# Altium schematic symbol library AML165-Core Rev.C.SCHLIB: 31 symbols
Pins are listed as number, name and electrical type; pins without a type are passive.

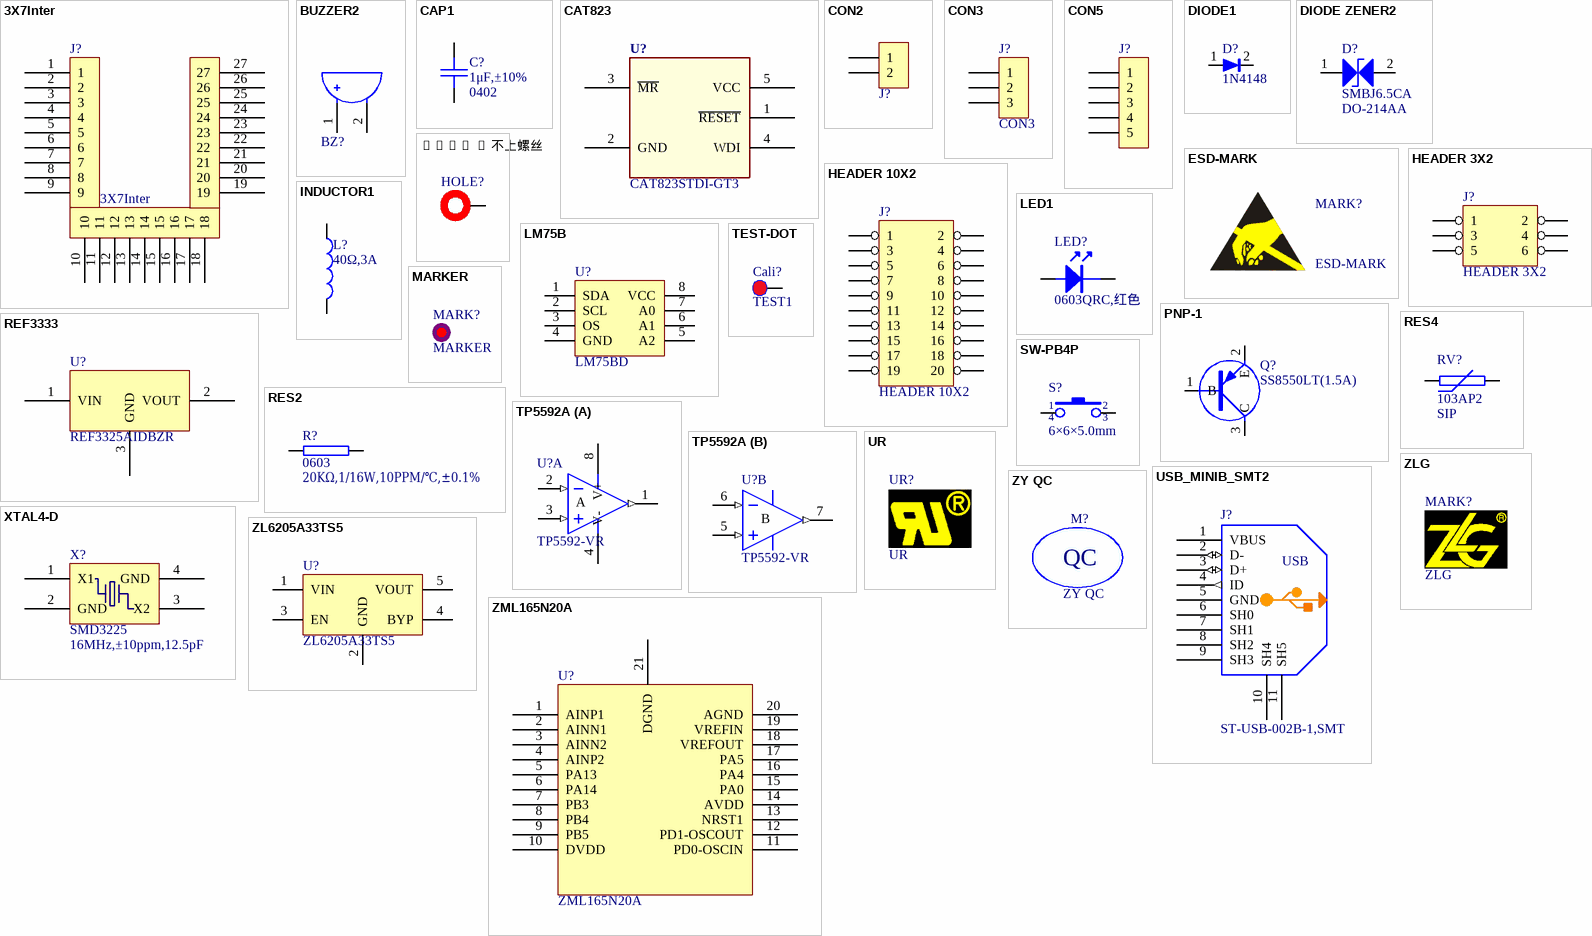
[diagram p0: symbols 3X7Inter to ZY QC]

## 3X7Inter
designator J?
物料代码: 1.10.11.0074
footprint SIP-27 2.54C (Footprint not found)
footprint SIP-27 2.54C
pins: 1, 2, 3, 4, 5, 6, 7, 8, 9, 10, 11, 12, 13, 14, 15, 16, 17, 18, 19, 20, 21, 22, 23, 24, 25, 26, 27

## BUZZER2
designator BZ?  (value not drawn)
Buzzer有极性; 物料代码: 1.06.09.0016; Value: AS-905I-LF,无源; 名称: 讯响器; 厂商: 常州笠翔; 型号: AS-905I-LF,无源,Ф9×4.8mm; 贴片和直插: THT; PCB备注: Flq-Shcj-Twrj-150113; 器件优选方案: 量产物料,优先选用
footprint BUZZ-4/9
pins: 1 A, 2 B
2 alternate drawings of the same symbol

## CAP1
designator C?, comment 封装: 0402  (hidden comment: 1μF,±10%)
GRM155R61C105KA12D,1μF,±10% ,16V,X5R,0402,muRata,RoHS; 物料代码: 1.02.17.0092; 名称: 电容; 贴片和直插: SMT; PCB备注: 无数据手册，依据采购部提供的信息添加的封装。; 器件优选方案: 正常状态，可以选用
footprint 0402CL
footprint 0402C
pins: 1, 2
2 alternate drawings of the same symbol

## CAT823
designator U?, comment CAT823STDI-GT3
1.05.07.0025
footprint SOT-23-5
pins: 1 ~{RESET}, 2 GND, 3 ~{MR}, 4 WDI, 5 VCC

## CON2
designator J?, comment DG127-5.08-02P-14-00AH,180°  (value not drawn)
DG127-5.08-02P-14-00AH,180°,绿色,DEGSON,RoHS; 物料代码: 1.10.06.0070; 名称: 端子; 贴片和直插: THT; PCB备注: xhm-lq-wyy-150126 yyf改名称180925; 器件优选方案: 正常状态，可以选用
footprint CON508P1016L810W110D15S-2DIP
pins: 1, 2
2 alternate drawings of the same symbol

## CON3
designator J?
Connector
footprint SIP-3-2.54
pins: 1, 2, 3
2 alternate drawings of the same symbol

## CON5
designator J?
Connector; 物料代码: 1.10.03.0015
footprint SIP-5-2.54-6.0-R90 (引脚伸出部分为6.0mm)
pins: 1, 2, 3, 4, 5
2 alternate drawings of the same symbol

## DIODE1
designator D?  value 1N4148  (hidden comment: DIODE1)
1N4148,SOD-323,RoHS; 物料代码: 1.04.07.0027; 名称: 二极管; 设备封装名称: SOD-323_1N4148; 贴片和直插: SMT
footprint SOD-323
pins: 1, 2
2 alternate drawings of the same symbol

## DIODE ZENER2
designator D?, comment 封装: DO-214AA  (hidden comment: SMBJ6.5CA)
SMBJ6.5CA,DO-214AA,君耀,RoHS; 物料代码: 1.04.03.0003; 名称: TVS瞬态抑制二极管; 设备封装名称: DO-214AA_SMBJ6.5CA; 贴片和直插: SMT; 器件优选方案: 正常状态，可以选用
footprint SOD-1812
pins: 1 A, 2 K
2 alternate drawings of the same symbol

## ESD-MARK
designator MARK?
footprint ZY_ESD-7
2 alternate drawings of the same symbol

## HEADER 3X2
designator J?
footprint IDC-6-2.54
pins: 1, 2, 3, 4, 5, 6
2 alternate drawings of the same symbol

## HEADER 10X2
designator J?
物料代码: 1.10.03.0016
footprint IDC-20-2.54-R90
pins: 1, 2, 3, 4, 5, 6, 7, 8, 9, 10, 11, 12, 13, 14, 15, 16, 17, 18, 19, 20
2 alternate drawings of the same symbol

## HOLE - 不上螺丝
designator HOLE?  (no BOM)
footprint HOLE-2.2
footprint HOLE-3.2
pins: 1

## INDUCTOR1
designator L?, comment 40Ω,3A
40Ω,3A,DCR35mΩ,BH03Y314S-40R,SMD,0603,丰晶,RoHS; 物料代码: 1.03.03.0011; 名称: 磁珠; 封装: 0603; 贴片和直插: SMT; 器件优选方案: 正常状态，可以选用
footprint 0603L
pins: 1, 2
2 alternate drawings of the same symbol

## LED1
designator LED?, comment 0603QRC,红色
0603QRC,红色,0603,创光,RoHS; 物料代码: 1.04.05.0008; 名称: 发光二极管; 封装: 0603; 设备封装名称: LED0603-RED; 贴片和直插: SMT; 器件优选方案: 正常状态，可以选用
footprint LED-0603
pins: 1, 2
2 alternate drawings of the same symbol

## LM75B
designator U?  value LM75BD  (hidden comment: LM75B)
LM75BD,SO-9,NXP,RoHS; 物料代码: 1.05.10.0602; 名称: IC; 封装: SO-8; 贴片和直插: SMT; 器件优选方案: 样品物料,谨慎选用
footprint SOIC127P600X175-8N
pins: 1 SDA, 2 SCL, 3 OS, 4 GND, 5 A2, 6 A1, 7 A0, 8 VCC
2 alternate drawings of the same symbol

## MARKER
designator MARK?  (no BOM)
footprint MARKER-C-1.0M
footprint MARKER-C-0.8M
pins: 0

## PNP-1
designator Q?  value SS8550LT(1.5A)  (hidden comment: PNP-1)
PNP Transistor; 物料代码: 1.04.09.0002; 名称: 三极管; 封装: SOT-23; 设备封装名称: SOT-23_SS8550LT; 厂商: 江苏长电; 贴片和直插: SMT
footprint SOT-23
pins: 1 B, 2 E, 3 C
2 alternate drawings of the same symbol

## REF3333
designator U?, comment REF3325AIDBZR
REF3325AIDBZR,SOT-23,TI; 物料代码: 1.05.10.0334; 名称: 集成电路; 设备封装名称: SOT-23_REF3325AIDBZR; 贴片和直插: SMT; 器件优选方案: 量产物料,优先选用
footprint SOT-23
pins: 1 VIN, 2 VOUT, 3 GND
2 alternate drawings of the same symbol

## RES2
designator R?, comment 封装: 0603  型号: 20KΩ,1/16W,10PPM/℃,±0.1%  (hidden comment: 20KΩ,1/16W)
20KΩ,1/16W,10PPM/℃,±0.1%,0603,Viking,RoHS; 物料代码: 1.01.01.0207; 名称: 电阻; 贴片和直插: SMT; 器件优选方案: 临时/偏门物料/不主推物料，谨慎选用
footprint 0603R
pins: 1, 2
2 alternate drawings of the same symbol

## RES4
designator RV?, comment 封装: SIP  (hidden comment: 103AP2)
103AP2,SIP,semitec,RoHS; 物料代码: 1.01.14.0020; 名称: 热敏电阻(临时); 贴片和直插: THT; PCB备注: 171205CZY; 器件优选方案: 临时/偏门物料/不主推物料，谨慎选用
footprint RESRR254W35L380T260H850P
pins: 1, 2

## SW-PB4P
designator S?, comment 6×6×5.0mm
TS0641-0501B,6×6×5.0mm,黑色,SMD,卷带装,RoHS; 物料代码: 1.09.01.0003; 名称: 轻触开关; 贴片和直插: SMT; 器件优选方案: 正常状态，可以选用
footprint KEY-6S
pins: 1, 2, 3, 4
2 alternate drawings of the same symbol

## TEST-DOT
designator Cali?, comment TEST1  (no BOM)
footprint PAD-40 (TEST-P)
footprint PAD-50 (TEST-P)
footprint PAD-25/40
footprint PAD-35/50
pins: 1

## TP5592A
designator U?, comment TP5592-VR
TP5592-VR,MSOP-8,3PEAK,RoHS; 物料代码: 1.05.20.0102; 名称: 集成电路(临时); 贴片和直插: SMT; PCB备注: 170810lmd; 器件优选方案: 临时/偏门物料/不主推物料，谨慎选用
footprint SOP65P490X120-8N
part A pins: 1 OUT (out), 2 IN- (in), 3 IN+ (in), 4 V- (power), 8 V+ (power)
part B pins: 5 IN+ (in), 6 IN- (in), 7 OUT (out)

## UR
designator UR?
footprint ZY_UR-3X2
footprint ZY_UR-4X3

## USB_MINIB_SMT2
designator J?, comment ST-USB-002B-1,SMT
ST-USB-002B-1,SMT,SUNGTECH,MicroUSB-A; 物料代码: 20.02.00033; 名称: 连接器; PCB备注: 190710lmd; 器件优选方案: 通用物料
footprint MICROUSB-ST-USB-002B-1
pins: 1 VBUS, 2 D- (io), 3 D+ (io), 4 ID (out), 5 GND (power), 6 SH0, 7 SH1, 8 SH2, 9 SH3, 10 SH4, 11 SH5

## XTAL4-D
designator X?, comment 封装: SMD3225  型号: 16MHz,±10ppm,12.5pF  (hidden comment: JYD3A1C7G5-12.5-16.000,16.0000MHz)
JYD3A1C7G5-12.5-16.000,16.0000MHz,±10ppm,12.5pF,-40~85℃,SMD3225,JYEG,RoHS; 物料代码: 1.07.03.0077; 名称: 晶体; 贴片和直插: SMT; PCB备注: 151225lmd171128ZW; 器件优选方案: 正常状态，可以选用
footprint OSCCC250X320X80-4N
pins: 1 X1, 2 GND, 3 X2, 4 GND

## ZL6205A33TS5
designator U?
ZL6205A33TS5,SOT-23-5,ZLG; 物料代码: 08.09.03069; 名称: 集成电路; 贴片和直插: SMT; PCB备注: 190806hcj; 器件优选方案: 待导入物料
footprint SOT-23-5
pins: 1 VIN, 2 GND, 3 EN, 4 BYP, 5 VOUT

## ZLG
designator MARK?  (no BOM)
footprint ZLG0.7 (Footprint not found)
footprint ZLG1.0
footprint ZLG1.5
footprint ZLG2.0

## ZML165N20A
designator U?
物料代码: 89.12.00028; 名称: 集成电路; 厂商: ZHIYUAN; 贴片和直插: SMT; PCB备注: 200721hcj
footprint QFN50P400X400X85-21N
pins: 1 AINP1, 2 AINN1, 3 AINN2, 4 AINP2, 5 PA13, 6 PA14, 7 PB3, 8 PB4, 9 PB5, 10 DVDD, 11 PD0-OSCIN, 12 PD1-OSCOUT, 13 NRST1, 14 AVDD, 15 PA0, 16 PA4, 17 PA5, 18 VREFOUT, 19 VREFIN, 20 AGND, 21 DGND

## ZY QC
designator M?  (no BOM)
footprint ZY_QC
